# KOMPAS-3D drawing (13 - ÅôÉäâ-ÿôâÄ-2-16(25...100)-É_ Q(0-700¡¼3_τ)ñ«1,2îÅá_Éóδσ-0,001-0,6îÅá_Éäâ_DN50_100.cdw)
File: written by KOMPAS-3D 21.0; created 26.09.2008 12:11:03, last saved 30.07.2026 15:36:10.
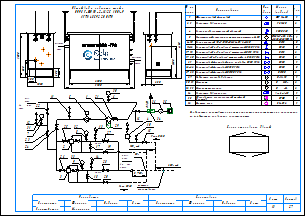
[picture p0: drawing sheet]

Sheets 1-2: A3, landscape

Document properties: Наименование: Макро:21; Автор: RaskoAdmin; Форматы листов документа: 2xA3; Полное имя файла: \\ur38nt01\Departments\КТО\КБ ПУРДГ\Заявки\Прайс-лист на типовые шкафы ГРПШ\ПУРДГ_стандарт_30_04_2026\ПУРДГ с РДГ(Н, В)\ПУРДГ-ШУГО-2-16(25...100)-Р_ Q(0-700нм3_ч)до1,2МПа_Рвых-0,001-0,6МПа_РДГ_DN50_100.cdw

Title block, sheet 1: Наименование: Пункт учета газа / ПУГ-Ш-400-Р / ЛГТИ.485922.001ТУ; designation: ЛГТИ.03.4411141; sheet number: 1; Количество листов документа: 2; organisation: ООО "ЭЛЬСТЕР Газэлектроника"; Форматы листов документа: A3; stored path: C:\Рабочие документы\Компас\ПУГ\Схема.cdw; Разработал: Устинов; Проверил: Кошкин; Утвердил: Кошкин
Title block, sheet 2: sheet number: 2; stored path: D:\Рабочие документы\Заявки\ПУРДГ\ПУРДГ-ШУЭО-2-100-Р 4411220.cdw; designation, second copy: ЛГТИ.03.4411141-

Views: Вид 1, Вид 2
Referenced files: wcvoit.frw
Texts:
  Normal
  № на
  схеме
  Усл.
  обозн.
  Марка
  (модель)
  Кол.
  Фильтр газовый фланцевый
  ФГ 16-50
  Регулятор давления газа
  РДГ-50
  Клапан предохранительный сбросной
  КПС DN20
  Измерительный комплекс с ротационным счетчиком Ду50
  СГ-ЭК-Р-(0,2...2,0)-
  Кран кнопочный VE-РАСКО-НЗ-1,6-G1/2-М20
  DN15
  Кран шаровой "под приварку" штуцерный DN20 PN16
  DN20
  Кран шаровой "под приварку" штуцерный DN15 PN16
  Кран шаровой "под приварку" штуцерный п/п DN20 PN16
  Кран шаровой фланцевый с мех. приводом DN50 PN16
  Кран шаровой фланцевый DN50 PN16
  Кран шаровой фланцевый DN100 PN16
  DN50
  DN100
  Индикатор перепада давления
  Манометр
  Манометр-напоромер
  Обогреватель газогорелочный шкафной
  (Эльтон")
  Счетчик газа
  Delta 15
  0...     МПа
  0...     кПа
  Venio-A-15
  ОГШН
  BK-G1,6
  Общий вид и габариты шкафа
  ПУРДГ-ШУГО-2-16(25...100)-Р
  Выход газа
  Вход газа
  logo-rasko-ge.png
  DN 1
  местное
  сопротивление
  Римп DN20
  Выход
  газа
  Р=     кПа
  Вход
  Р=       МПа
  PDI
  Схема открывания дверей
  Предприятие изготовитель может заменять комплектующие на аналогичные,
  не ухудшающие заявленных характеристик.
  Должность
  Конструктор
  Фамилия
  Подпись
  Дата
  Согласовано
  Максимкин
  Лист
  Листов
  POLYLINE_STYLE_0.18_RGB_0_0_0
  POLYLINE_STYLE_0.50_RGB_0_0_0
  POLYLINE_STYLE_0.34_RGB_0_0_0
  PHANTOM_RGB_0_0_0_SC_1_THICK_0.18
  K5LT_THIN_RGB_0_0_0_THICK_0.18
  K5LT32769_RGB_0_0_0_THICK_0.18
  K5LT12_RGB_0_0_0_SC_1_THICK_0.18
  K5LT_DASHED_RGB_0_0_0_SC_1_THICK_0.18
  ACISOTGL_RGB_0_0_0_SC_0.8_THICK_0.25
  CONTINUOUS_RGB_0_127_31_THICK_0.3
  CONTINUOUS_RGB_0_0_255_THICK_0.35
  CONTINUOUS_RGB_255_0_0_THICK_0.35
  POLYLINE_STYLE_0.25_RGB_0_0_0
  CONTINUOUS_RGB_0_0_0_THICK_0.5
  POLYLINE_STYLE_0.35_RGB_0_0_255
  CONTINUOUS_RGB_0_0_0_THICK_0.4
  CONTINUOUS_RGB_0_0_0_THICK_0.35
  НЕВИДИМАЯ_RGB_0_0_0_SC_0.3_THICK_0.25
  СONTINUOUS_RGB_0_0_0_THICK_0.25
  ОСЕВАЯ2_RGB_248_153_30_SC_0.3_THICK_0.25
  Без оформления
Dimensions and other numbers on the sheet: 1; 2, 3; 2; 4; 5; 6-10; 11-16; 17, 18; 19, 20; 21; 22-26; 27, 28; 29; 30, 31; 32, 33; 34; 35; 36; 1500; 250; 300; 1050; 550; 305; 2800; 4130; 2000; 3100; 5,,,7DN 1; 7; 31; 12; 22; 23; 24; 11; 6; 30; 25; 32; 8; 13; 27; 19; 10; 15; 26; 33; 9; 3; 14; 28; 20; 17; 18; 16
